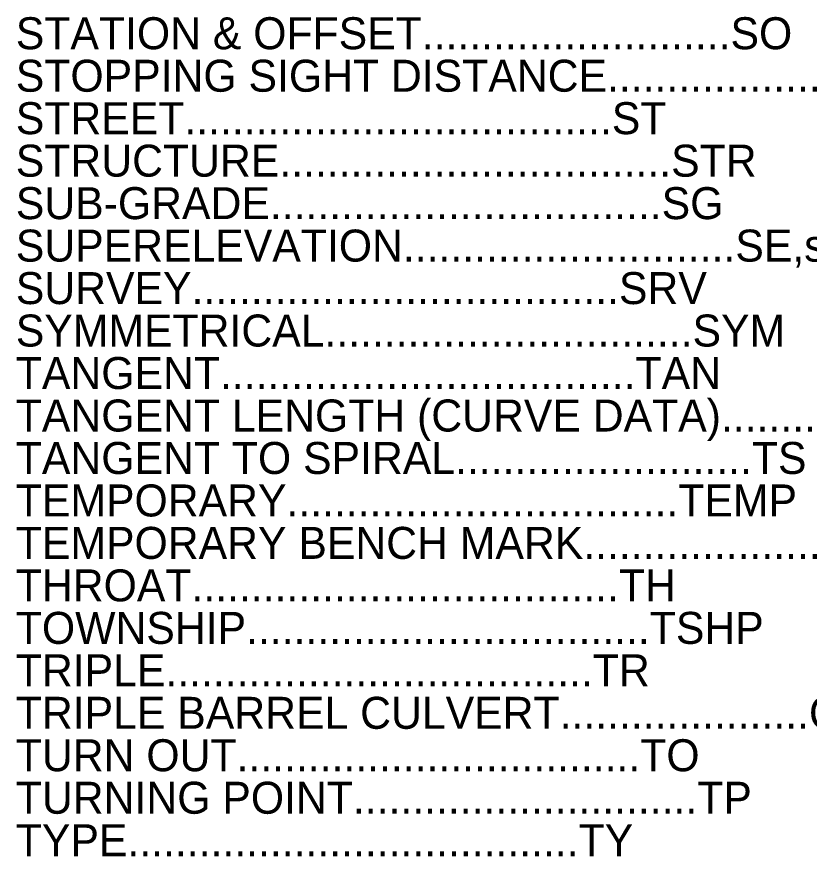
# Model space of a CAD drawing. Extents: x 0 to 1700, y 31 to 1131.
# Drawn here: x 901.8 to 1075.4, y 214.1 to 397.9 of the extents above; entities that cross this region are included whole.
import ezdxf

# ---------------------------------------------------------------- set-up
doc = ezdxf.new("R2010")
doc.units = 0
doc.layers.add('Level 1', color=7, linetype='Continuous')

msp = doc.modelspace()

# ---------------------------------------------------------------- texts
at = {"layer": 'Level 1'}
for s, p in [('STATION & OFFSET..........................SO', (901.56, 390.75)), ('STOPPING SIGHT DISTANCE...................SSD', (901.56, 381.45)), ('STREET....................................ST', (901.56, 372.16)), ('STRUCTURE.................................STR', (901.56, 362.86)), ('SUB-GRADE.................................SG', (901.56, 353.56)), ('SUPERELEVATION............................SE,se or e', (901.56, 344.27)), ('SURVEY....................................SRV', (901.56, 334.97)), ('SYMMETRICAL...............................SYM', (901.56, 325.68)), ('TANGENT...................................TAN', (901.56, 316.38)), ('TANGENT LENGTH (CURVE DATA)...............T', (901.56, 307.08)), ('TANGENT TO SPIRAL.........................TS', (901.56, 297.79)), ('TEMPORARY.................................TEMP', (901.56, 288.49)), ('TEMPORARY BENCH MARK......................TBM', (901.56, 279.2)), ('THROAT....................................TH', (901.56, 269.9)), ('TOWNSHIP..................................TSHP', (901.56, 260.6)), ('TRIPLE....................................TR', (901.56, 251.31)), ('TRIPLE BARREL CULVERT.....................CT', (901.56, 242.01)), ('TURN OUT..................................TO', (901.56, 232.72)), ('TURNING POINT.............................TP', (901.56, 223.42)), ('TYPE......................................TY', (901.56, 214.12))]:
    msp.add_text(s, height=7, dxfattribs=at).set_placement(p)

doc.saveas('drawing.dxf')
